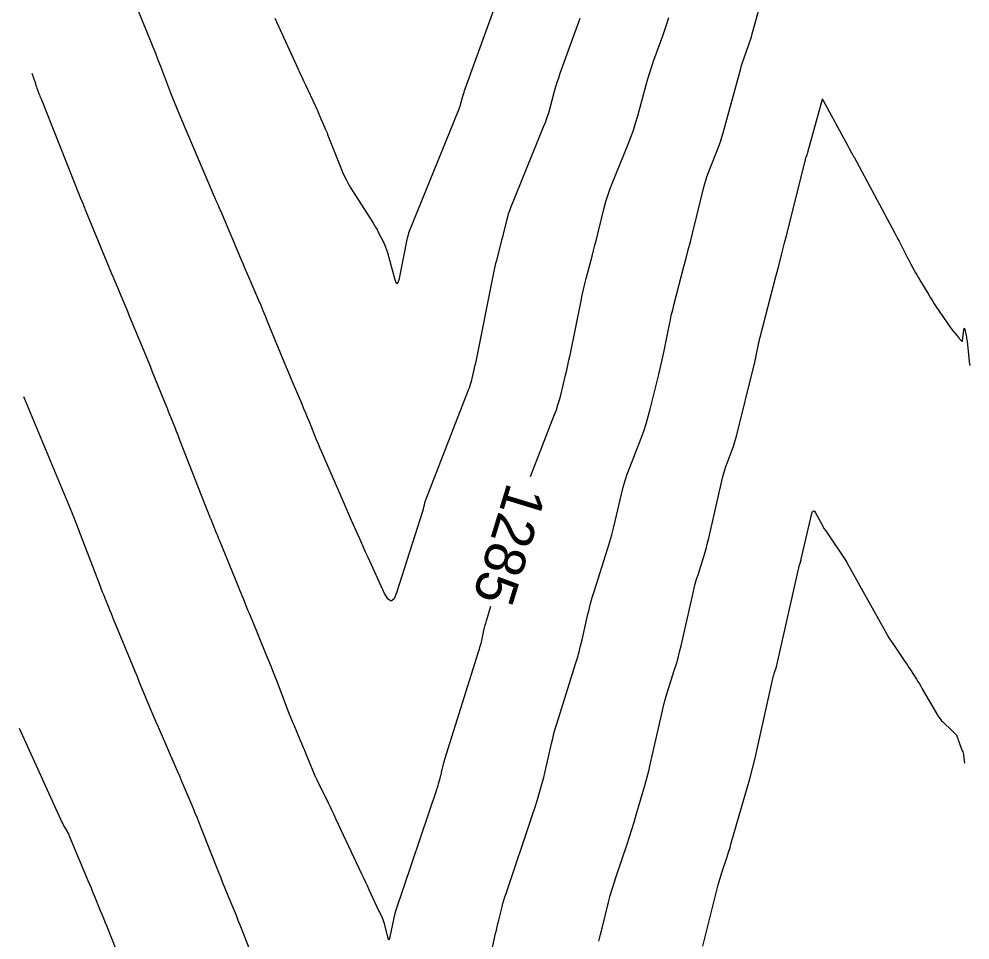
# Model space of a CAD drawing. Extents: x 658976 to 668721, y 639543 to 647196.
# Drawn here: x 661401.6 to 661542, y 639999.3 to 640135.2 of the extents above; entities that cross this region are included whole.
import ezdxf

# ---------------------------------------------------------------- set-up
doc = ezdxf.new("R2010")
doc.units = 0
for name, color, linetype in [('Ex_Contour Labels', 7, 'Continuous'), ('Ex_Major Contours', 7, 'Continuous'), ('Ex_Minor Contours', 7, 'Continuous')]:
    doc.layers.add(name, color=color, linetype=linetype)

msp = doc.modelspace()

# ---------------------------------------------------------------- linework, layer by layer
at = {"layer": 'Ex_Major Contours'}
for points in [[(661477.12, 640067.71), (661480.68, 640076.87), (661480.94, 640077.57), (661481.18, 640078.29), (661481.39, 640079.01), (661481.59, 640079.74), (661482.31, 640082.66), (661482.48, 640083.4), (661482.65, 640084.13), (661482.81, 640084.87), (661482.96, 640085.61), (661484.59, 640093.65), (661484.77, 640094.48), (661484.95, 640095.31), (661485.15, 640096.13), (661485.36, 640096.95), (661486.22, 640100.24), (661486.43, 640101.06), (661486.64, 640101.88), (661486.85, 640102.7), (661487.05, 640103.53), (661488.01, 640107.38), (661488.25, 640108.29), (661488.53, 640109.19), (661488.84, 640110.08), (661489.18, 640110.96), (661491.54, 640116.77), (661491.94, 640117.8), (661492.31, 640118.84), (661492.65, 640119.89), (661492.96, 640120.95), (661494.21, 640125.51), (661494.47, 640126.43), (661494.75, 640127.34), (661495.04, 640128.25), (661495.36, 640129.15), (661496.66, 640132.74), (661496.98, 640133.64), (661497.27, 640134.55), (661497.56, 640135.46)], [(661403.47, 640127.27), (661403.96, 640125.85), (661404.03, 640125.65), (661404.1, 640125.45), (661404.17, 640125.25), (661404.24, 640125.05), (661404.54, 640124.25), (661404.62, 640124.05), (661404.69, 640123.85), (661404.77, 640123.65), (661404.85, 640123.45), (661410.47, 640109.31), (661410.48, 640109.27), (661410.5, 640109.23), (661410.52, 640109.19), (661410.54, 640109.15), (661410.6, 640108.98), (661410.62, 640108.94), (661410.64, 640108.89), (661410.66, 640108.85), (661410.67, 640108.81), (661411.06, 640107.9), (661411.13, 640107.73), (661411.19, 640107.57), (661411.26, 640107.4), (661411.33, 640107.24), (661415.27, 640097.68), (661415.49, 640097.16), (661415.7, 640096.64), (661415.92, 640096.11), (661416.14, 640095.59), (661417.01, 640093.51), (661417.23, 640092.99), (661417.45, 640092.47), (661417.66, 640091.95), (661417.88, 640091.43), (661420.27, 640085.66), (661420.61, 640084.83), (661420.95, 640084.01), (661421.28, 640083.18), (661421.62, 640082.35), (661423.28, 640078.23), (661423.45, 640077.8), (661423.62, 640077.38), (661423.79, 640076.96), (661423.96, 640076.53), (661424.64, 640074.83), (661424.81, 640074.41), (661424.98, 640073.98), (661425.15, 640073.56), (661425.31, 640073.13), (661429.48, 640062.47), (661429.52, 640062.38), (661429.55, 640062.29), (661429.59, 640062.2), (661429.62, 640062.11), (661429.76, 640061.75), (661429.79, 640061.66), (661429.83, 640061.57), (661429.87, 640061.49), (661429.9, 640061.4), (661430.63, 640059.63), (661430.76, 640059.31), (661430.89, 640058.99), (661431.02, 640058.66), (661431.16, 640058.34), (661434, 640051.4), (661434.17, 640050.98), (661434.34, 640050.56), (661434.51, 640050.14), (661434.68, 640049.72), (661435.36, 640048.04), (661435.54, 640047.62), (661435.71, 640047.2), (661435.88, 640046.78), (661436.05, 640046.36), (661438.06, 640041.49), (661438.44, 640040.56), (661438.82, 640039.63), (661439.19, 640038.69), (661439.55, 640037.75), (661441.3, 640033.19), (661441.51, 640032.65), (661441.72, 640032.11), (661441.94, 640031.57), (661442.17, 640031.04), (661443.07, 640028.9), (661443.29, 640028.37), (661443.52, 640027.83), (661443.74, 640027.3), (661443.96, 640026.76), (661445.35, 640023.44), (661445.36, 640023.4), (661445.38, 640023.36), (661445.4, 640023.32), (661445.42, 640023.27), (661445.52, 640023.07), (661445.56, 640022.98), (661445.58, 640022.94), (661447.24, 640019.55), (661447.52, 640018.97), (661447.8, 640018.39), (661448.08, 640017.81), (661448.35, 640017.22), (661452.18, 640009.06), (661452.45, 640008.48), (661452.72, 640007.91), (661452.99, 640007.33), (661453.26, 640006.75), (661454.75, 640003.56), (661454.82, 640003.42), (661454.88, 640003.28), (661454.94, 640003.15), (661455.01, 640003.01), (661455.26, 640002.46), (661455.32, 640002.32), (661455.37, 640002.18), (661455.42, 640002.04), (661455.46, 640001.9), (661456.01, 639999.74), (661456.11, 639999.44), (661456.21, 639999.34), (661456.3, 639999.44), (661456.39, 639999.75), (661457.15, 640003.27), (661457.16, 640003.3), (661457.17, 640003.33), (661457.17, 640003.35), (661457.18, 640003.38), (661457.21, 640003.5), (661457.22, 640003.53), (661457.22, 640003.56), (661457.23, 640003.58), (661457.24, 640003.61), (661463.28, 640021.51), (661463.35, 640021.72), (661463.42, 640021.92), (661463.48, 640022.13), (661463.54, 640022.34), (661463.79, 640023.19), (661463.85, 640023.4), (661463.9, 640023.61), (661463.96, 640023.82), (661464, 640024.04), (661464.23, 640025.03), (661464.28, 640025.27), (661464.34, 640025.5), (661464.41, 640025.74), (661464.48, 640025.97), (661469.46, 640041.84), (661469.59, 640042.25), (661469.71, 640042.67), (661469.82, 640043.09), (661469.92, 640043.52), (661470.3, 640045.22), (661470.4, 640045.64), (661470.51, 640046.06), (661470.63, 640046.48), (661470.76, 640046.9), (661471.29, 640048.58)]]:
    msp.add_lwpolyline(points, dxfattribs=at)
at = {"layer": 'Ex_Minor Contours'}
for points in [[(661469.01, 639986.53), (661471.98, 640000.24), (661472.09, 640000.73), (661472.2, 640001.23), (661472.32, 640001.72), (661472.44, 640002.22), (661472.94, 640004.2), (661473.06, 640004.69), (661473.2, 640005.18), (661473.35, 640005.67), (661473.51, 640006.15), (661477.33, 640017.47), (661477.54, 640018.11), (661477.75, 640018.76), (661477.95, 640019.4), (661478.14, 640020.05), (661478.89, 640022.64), (661479.07, 640023.29), (661479.24, 640023.95), (661479.41, 640024.6), (661479.56, 640025.26), (661480.24, 640028.32), (661480.41, 640029.05), (661480.59, 640029.77), (661480.79, 640030.49), (661481.01, 640031.21), (661483.79, 640040.05), (661484.05, 640040.93), (661484.3, 640041.81), (661484.53, 640042.7), (661484.75, 640043.6), (661485.56, 640047.19), (661485.77, 640048.08), (661486, 640048.97), (661486.25, 640049.85), (661486.52, 640050.73), (661488.55, 640057.14), (661488.85, 640058.12), (661489.13, 640059.11), (661489.39, 640060.1), (661489.63, 640061.11), (661490.56, 640065.12), (661490.81, 640066.12), (661491.09, 640067.1), (661491.41, 640068.08), (661491.77, 640069.05), (661493.45, 640073.38), (661493.84, 640074.42), (661494.2, 640075.48), (661494.51, 640076.55), (661494.8, 640077.63), (661496.07, 640082.79), (661496.27, 640083.65), (661496.47, 640084.51), (661496.66, 640085.38), (661496.84, 640086.25), (661497.55, 640089.73), (661497.73, 640090.59), (661497.92, 640091.46), (661498.13, 640092.32), (661498.35, 640093.18), (661499.79, 640098.73), (661500.11, 640099.94), (661500.42, 640101.15), (661500.73, 640102.36), (661501.03, 640103.58), (661502.78, 640110.6), (661502.96, 640111.28), (661503.16, 640111.94), (661503.39, 640112.59), (661503.64, 640113.24), (661504.68, 640115.82), (661504.93, 640116.46), (661505.17, 640117.12), (661505.38, 640117.78), (661505.57, 640118.44), (661508.18, 640127.96), (661508.3, 640128.39), (661508.43, 640128.82), (661508.57, 640129.24), (661508.72, 640129.66), (661509.33, 640131.34), (661509.48, 640131.76), (661509.62, 640132.18), (661509.75, 640132.61), (661509.87, 640133.04), (661512.92, 640144.08)], [(661439.38, 640135.37), (661442.81, 640127.85), (661443.07, 640127.27), (661443.34, 640126.69), (661443.61, 640126.11), (661443.88, 640125.53), (661445.31, 640122.47), (661445.41, 640122.26), (661445.51, 640122.04), (661445.61, 640121.82), (661445.7, 640121.61), (661446.18, 640120.51), (661446.45, 640119.88), (661446.82, 640119.05), (661446.91, 640118.84), (661446.99, 640118.63), (661447.08, 640118.42), (661447.16, 640118.21), (661449.1, 640113.28), (661449.48, 640112.39), (661449.89, 640111.53), (661450.34, 640110.69), (661450.84, 640109.88), (661453.83, 640105.21), (661454.05, 640104.86), (661454.26, 640104.51), (661454.46, 640104.15), (661454.65, 640103.78), (661455.4, 640102.32), (661455.58, 640101.95), (661455.73, 640101.57), (661455.87, 640101.19), (661455.99, 640100.79), (661457.03, 640096.94), (661457.23, 640096.36), (661457.42, 640096.17), (661457.6, 640096.37), (661457.77, 640096.96), (661458.97, 640102.92), (661458.98, 640102.96), (661458.99, 640103), (661459, 640103.05), (661459.01, 640103.09), (661459.06, 640103.26), (661459.07, 640103.3), (661459.08, 640103.34), (661459.09, 640103.39), (661459.1, 640103.43), (661459.15, 640103.63), (661459.16, 640103.68), (661459.18, 640103.73), (661459.19, 640103.77), (661459.21, 640103.82), (661466.5, 640121.74), (661466.6, 640122), (661466.69, 640122.26), (661466.78, 640122.53), (661466.85, 640122.79), (661467.15, 640123.87), (661467.22, 640124.14), (661467.31, 640124.41), (661467.39, 640124.67), (661467.49, 640124.93), (661472.37, 640138.43)], [(661484.42, 640135.33), (661481.47, 640127.18), (661481.25, 640126.53), (661481.03, 640125.87), (661480.83, 640125.21), (661480.64, 640124.55), (661479.91, 640121.87), (661479.71, 640121.21), (661479.5, 640120.55), (661479.27, 640119.9), (661479.02, 640119.26), (661474.19, 640107.39), (661474.02, 640106.93), (661473.85, 640106.46), (661473.71, 640105.98), (661473.58, 640105.5), (661473.08, 640103.48), (661472.97, 640103.05), (661472.86, 640102.61), (661472.75, 640102.18), (661472.64, 640101.75), (661472.19, 640100.02), (661472.08, 640099.59), (661471.97, 640099.15), (661471.87, 640098.72), (661471.78, 640098.28), (661468.98, 640084.42), (661468.91, 640084.09), (661468.83, 640083.75), (661468.76, 640083.42), (661468.68, 640083.08), (661468.35, 640081.75), (661468.26, 640081.42), (661468.16, 640081.09), (661468.06, 640080.76), (661467.94, 640080.44), (661461.62, 640064.21), (661461.57, 640064.08), (661461.53, 640063.95), (661461.49, 640063.81), (661461.45, 640063.67), (661461.33, 640063.12), (661461.29, 640062.98), (661461.26, 640062.84), (661461.22, 640062.71), (661461.18, 640062.57), (661457.36, 640050.53), (661456.97, 640049.65), (661456.55, 640049.33), (661456.09, 640049.59), (661455.59, 640050.42), (661453.14, 640055.78), (661452.83, 640056.46), (661452.52, 640057.14), (661452.22, 640057.82), (661451.91, 640058.5), (661450.7, 640061.22), (661450.4, 640061.9), (661450.1, 640062.59), (661449.8, 640063.27), (661449.5, 640063.95), (661446.64, 640070.54), (661446.36, 640071.19), (661446.08, 640071.84), (661445.81, 640072.49), (661445.54, 640073.14), (661444.48, 640075.76), (661444.21, 640076.41), (661443.94, 640077.07), (661443.67, 640077.72), (661443.39, 640078.37), (661442.13, 640081.33), (661441.83, 640082.04), (661441.53, 640082.75), (661441.23, 640083.46), (661440.94, 640084.17), (661438.3, 640090.61), (661437.98, 640091.39), (661437.65, 640092.16), (661437.33, 640092.94), (661437, 640093.71), (661435.67, 640096.8), (661435.34, 640097.57), (661435.01, 640098.35), (661434.68, 640099.12), (661434.35, 640099.9), (661431.38, 640106.91), (661431.3, 640107.09), (661431.23, 640107.26), (661431.15, 640107.43), (661431.08, 640107.61), (661430.77, 640108.3), (661430.7, 640108.47), (661430.62, 640108.64), (661430.55, 640108.81), (661430.47, 640108.99), (661425.59, 640120.44), (661425.19, 640121.4), (661424.79, 640122.37), (661424.41, 640123.33), (661424.03, 640124.31), (661422.53, 640128.22), (661422.15, 640129.18), (661421.78, 640130.15), (661421.39, 640131.11), (661421, 640132.07), (661419.24, 640136.41)], [(661487.24, 639999.13), (661487.47, 640000.09), (661487.71, 640001.05), (661488.66, 640004.89), (661488.91, 640005.85), (661489.18, 640006.8), (661489.47, 640007.75), (661489.78, 640008.69), (661491.38, 640013.44), (661491.73, 640014.51), (661492.08, 640015.59), (661492.41, 640016.67), (661492.73, 640017.75), (661493.99, 640022.1), (661494.3, 640023.19), (661494.58, 640024.28), (661494.86, 640025.38), (661495.11, 640026.48), (661496.4, 640032.3), (661496.61, 640033.18), (661496.83, 640034.05), (661497.07, 640034.92), (661497.33, 640035.78), (661498.41, 640039.22), (661498.68, 640040.08), (661498.92, 640040.95), (661499.14, 640041.82), (661499.35, 640042.7), (661501.13, 640050.52), (661501.29, 640051.21), (661501.46, 640051.88), (661501.65, 640052.56), (661501.86, 640053.22), (661502.7, 640055.89), (661502.91, 640056.56), (661503.1, 640057.23), (661503.28, 640057.91), (661503.44, 640058.59), (661505.54, 640067.69), (661505.66, 640068.2), (661505.81, 640068.7), (661505.97, 640069.2), (661506.16, 640069.7), (661506.92, 640071.67), (661507.11, 640072.16), (661507.27, 640072.66), (661507.42, 640073.17), (661507.56, 640073.68), (661510.15, 640084.21), (661510.23, 640084.55), (661510.31, 640084.89), (661510.38, 640085.23), (661510.45, 640085.57), (661510.73, 640086.94), (661510.8, 640087.28), (661510.88, 640087.62), (661510.96, 640087.96), (661511.04, 640088.29), (661513.37, 640097.22), (661513.79, 640098.82), (661514.2, 640100.42), (661514.6, 640102.02), (661515.01, 640103.62), (661517.71, 640114.51), (661517.74, 640114.6), (661517.76, 640114.69), (661517.79, 640114.78), (661517.83, 640114.87), (661517.97, 640115.21), (661518, 640115.3), (661518.03, 640115.39), (661518.06, 640115.48), (661518.09, 640115.57), (661520.24, 640123.41), (661520.25, 640123.43), (661520.25, 640123.44), (661520.26, 640123.43), (661520.26, 640123.41), (661520.29, 640123.3), (661520.29, 640123.28), (661520.3, 640123.25), (661520.31, 640123.23), (661520.32, 640123.2), (661523.91, 640116.64), (661524.18, 640116.13), (661524.54, 640115.47), (661524.57, 640115.42), (661524.6, 640115.37), (661524.63, 640115.32), (661524.66, 640115.26), (661524.78, 640115.06), (661524.81, 640115), (661524.84, 640114.95), (661524.87, 640114.9), (661524.9, 640114.85), (661530.92, 640103.63), (661531.13, 640103.24), (661531.34, 640102.84), (661531.55, 640102.44), (661531.75, 640102.05), (661532.65, 640100.29), (661532.81, 640099.98), (661532.98, 640099.66), (661533.14, 640099.35), (661533.31, 640099.04), (661533.99, 640097.79), (661534.17, 640097.48), (661534.34, 640097.17), (661534.52, 640096.87), (661534.7, 640096.56), (661535.93, 640094.52), (661536.2, 640094.08), (661536.47, 640093.64), (661536.75, 640093.21), (661537.04, 640092.78), (661539.1, 640089.76), (661539.23, 640089.58), (661539.36, 640089.4), (661539.49, 640089.23), (661539.63, 640089.06), (661540.37, 640088.17), (661540.42, 640088.11), (661540.47, 640088.05), (661540.52, 640087.99), (661540.58, 640087.93), (661540.8, 640087.71), (661540.84, 640087.67), (661540.88, 640087.66), (661540.91, 640087.69), (661540.92, 640087.75), (661541.11, 640089.38), (661541.14, 640089.55), (661541.17, 640089.6), (661541.21, 640089.55), (661541.25, 640089.39), (661541.45, 640088.54), (661541.49, 640088.32), (661541.53, 640088.11), (661541.56, 640087.89), (661541.59, 640087.67), (661541.9, 640084.71), (661541.9, 640084.65), (661541.91, 640084.59), (661541.92, 640084.53), (661541.94, 640084.46), (661542.02, 640084.1)], [(661402.26, 640079.54), (661409.4, 640062.39), (661409.41, 640062.35), (661409.43, 640062.31), (661409.44, 640062.27), (661409.46, 640062.23), (661409.51, 640062.08), (661409.53, 640062.04), (661409.54, 640062), (661409.56, 640061.96), (661409.57, 640061.93), (661413.57, 640051.51), (661413.73, 640051.1), (661413.89, 640050.7), (661414.05, 640050.3), (661414.21, 640049.9), (661414.86, 640048.31), (661415.03, 640047.91), (661415.19, 640047.51), (661415.36, 640047.11), (661415.52, 640046.71), (661418, 640040.65), (661418.34, 640039.82), (661418.68, 640039), (661419.02, 640038.18), (661419.36, 640037.35), (661420.73, 640034.06), (661421.08, 640033.24), (661421.42, 640032.42), (661421.77, 640031.6), (661422.13, 640030.78), (661424.62, 640025.05), (661424.95, 640024.28), (661425.28, 640023.51), (661425.61, 640022.74), (661425.94, 640021.96), (661427.24, 640018.87), (661427.57, 640018.09), (661427.88, 640017.32), (661428.2, 640016.54), (661428.51, 640015.76), (661431.05, 640009.31), (661431.33, 640008.6), (661431.61, 640007.89), (661431.9, 640007.18), (661432.19, 640006.47), (661433.35, 640003.64), (661433.64, 640002.94), (661433.93, 640002.23), (661434.21, 640001.52), (661434.49, 640000.81), (661437.81, 639992.34)], [(661502.59, 639998.38), (661504.85, 640007.42), (661504.98, 640007.93), (661505.12, 640008.43), (661505.28, 640008.93), (661505.44, 640009.43), (661506.11, 640011.42), (661506.27, 640011.92), (661506.43, 640012.41), (661506.59, 640012.92), (661506.73, 640013.42), (661509.09, 640021.55), (661509.52, 640023.08), (661509.92, 640024.61), (661510.31, 640026.15), (661510.66, 640027.7), (661512.92, 640037.89), (661512.97, 640038.11), (661513.03, 640038.33), (661513.09, 640038.55), (661513.16, 640038.77), (661513.43, 640039.64), (661513.5, 640039.86), (661513.56, 640040.08), (661513.62, 640040.3), (661513.67, 640040.52), (661516.87, 640054.66), (661516.89, 640054.73), (661516.91, 640054.8), (661516.93, 640054.87), (661516.95, 640054.94), (661517.04, 640055.22), (661517.06, 640055.29), (661517.08, 640055.36), (661517.1, 640055.43), (661517.11, 640055.5), (661518.67, 640062.26), (661518.77, 640062.55), (661518.89, 640062.65), (661519.04, 640062.58), (661519.21, 640062.34), (661519.93, 640061), (661520.12, 640060.66), (661520.31, 640060.34), (661520.51, 640060.01), (661520.72, 640059.69), (661523.72, 640055.21), (661523.73, 640055.2), (661523.74, 640055.18), (661523.75, 640055.17), (661523.75, 640055.16), (661523.79, 640055.1), (661523.79, 640055.09), (661523.8, 640055.08), (661523.81, 640055.06), (661523.82, 640055.05), (661523.85, 640054.99), (661523.86, 640054.97), (661523.87, 640054.96), (661523.88, 640054.94), (661523.89, 640054.93), (661529.43, 640044.97), (661529.73, 640044.44), (661530.04, 640043.92), (661530.37, 640043.41), (661530.71, 640042.9), (661532.31, 640040.56), (661532.54, 640040.22), (661532.77, 640039.87), (661533, 640039.53), (661533.22, 640039.18), (661534.12, 640037.8), (661534.34, 640037.45), (661534.56, 640037.1), (661534.77, 640036.75), (661534.98, 640036.39), (661537.24, 640032.48), (661537.42, 640032.19), (661537.62, 640031.92), (661537.83, 640031.67), (661538.07, 640031.43), (661539.41, 640030.17), (661539.47, 640030.11), (661539.53, 640030.04), (661539.6, 640029.98), (661539.66, 640029.92), (661539.93, 640029.64), (661539.98, 640029.58), (661540.02, 640029.52), (661540.06, 640029.46), (661540.09, 640029.39), (661540.2, 640029.12), (661540.22, 640029.05), (661540.25, 640028.98), (661540.28, 640028.91), (661540.3, 640028.84), (661540.89, 640027.23), (661540.95, 640027.05), (661541, 640026.88), (661541.04, 640026.69), (661541.07, 640026.51), (661541.19, 640025.4)], [(661401.6, 640030.56), (661407.99, 640016.58), (661408.07, 640016.42), (661408.15, 640016.26), (661408.23, 640016.1), (661408.32, 640015.95), (661408.69, 640015.33), (661408.78, 640015.17), (661408.87, 640015.01), (661408.94, 640014.85), (661409.01, 640014.69), (661411.77, 640008.1), (661412, 640007.54), (661412.23, 640006.99), (661412.46, 640006.43), (661412.69, 640005.87), (661413.6, 640003.65), (661413.83, 640003.09), (661414.05, 640002.53), (661414.28, 640001.98), (661414.5, 640001.42), (661418.83, 639990.47)]]:
    msp.add_lwpolyline(points, dxfattribs=at)

# ---------------------------------------------------------------- texts
at = {"layer": 'Ex_Contour Labels'}
msp.add_text('1285', height=6, rotation=253.0663, dxfattribs=at).set_placement((661473.76, 640066.99))

doc.saveas('drawing.dxf')
